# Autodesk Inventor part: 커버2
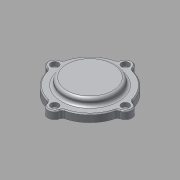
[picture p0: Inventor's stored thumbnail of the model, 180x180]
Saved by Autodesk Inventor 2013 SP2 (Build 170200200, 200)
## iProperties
Company: 한국ATC센터
Created: 2015-12
Part Number: 커버2
Document SubType Name: Modeling
Designer: mdu
Density: 2.71 g/cm^3
Material: 알루미늄 6061
Author: mdu
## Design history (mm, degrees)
sketch "스케치1"
  geometry: C1 r 1.621 at (0, 6.75) reference; C2 r 1.621 at (-37, -30.25) reference; C3 r 1.621 at (0, -67.25) reference; C4 r 1.621 at (37, -30.25) reference; C5 r 10 at (0, -30.25) reference; C6 r 12 at (0, -30.25); C7 r 24.5 at (0, -30.25) reference; A1 r 3 centre (-38.77, -20.408) between (-38.239, -23.361) and (-35.862, -21.146) reference; A2 r 7 centre (-37, -30.25) between (-38.239, -23.361) and (-38.239, -37.139) reference; A3 r 3 centre (-38.77, -40.092) between (-35.862, -39.354) and (-38.239, -37.139) reference; A4 r 37 centre (0, -30.25) between (-35.862, -39.354) and (-9.104, -66.113) reference; A5 r 3 centre (-9.842, -69.02) between (-6.889, -68.489) and (-9.104, -66.113) reference; A6 r 7 centre (0, -67.25) between (-6.889, -68.489) and (6.889, -68.489) reference; A7 r 3 centre (9.842, -69.02) between (9.104, -66.112) and (6.889, -68.489) reference; A8 r 37 centre (0, -30.25) between (9.104, -66.112) and (35.863, -39.354) reference; A9 r 3 centre (38.77, -40.092) between (38.239, -37.139) and (35.863, -39.354) reference; A10 r 7 centre (37, -30.25) between (38.239, -37.139) and (38.239, -23.361) reference; A11 r 3 centre (38.77, -20.408) between (35.863, -21.146) and (38.239, -23.361) reference; A12 r 37 centre (0, -30.25) between (35.863, -21.146) and (9.104, 5.612) reference; A13 r 3 centre (9.842, 8.52) between (6.889, 7.989) and (9.104, 5.612) reference; A14 r 7 centre (0, 6.75) between (6.889, 7.989) and (-6.889, 7.989) reference; A15 r 3 centre (-9.842, 8.52) between (-9.104, 5.612) and (-6.889, 7.989) reference; A16 r 37 centre (0, -30.25) between (-9.104, 5.612) and (-35.862, -21.146) reference; 1 further point
  constraints: 1 centre point, 1 coincident
  dimensions: "d2" = 2 radial gap between concentric circles of C6 C5
extrude "돌출1" new body sketch "스케치1" distance "d0" = 8; taper "d1" = 0 deg
sketch "스케치2"
  geometry: C1 r 23.5 at (0, -30.25) reference; C2 r 12 at (0, -30.25) reference; 1 further point
extrude "돌출2" join sketch "스케치2" distance "d4" = 5; taper "d5" = 0 deg
sketch "스케치3"
  geometry: C1 r 23.5 at (0, 0) reference; C2 r 20.5 at (0, 0); 1 further point
  constraints: 1 centre point
  dimensions: "d6" = 3 radial gap between concentric circles of C2 C1
node "작업 평면1"
extrude "돌출3" join sketch "스케치3" stored distance "d7" = 5; taper "d8" = 0 deg
fillet "모깎기1" dims "d9" = 3
sketch "스케치4"
  geometry: C1 r 12 at (0, -30.25) reference; C2 r 27 at (0, -30.25); 1 further point
  constraints: 1 centre point
  dimensions: "d10" = 15 radial gap between concentric circles of C1 C2
extrude "돌출4" join sketch "스케치4" distance "d11" = 7; taper "d12" = 0 deg
fillet "모깎기2" dims "d13" = 3
chamfer "모따기1" distance "d14" = 1; stored, may be unused: second distance "d15" = 2, angle "d16" = 45 deg
node "작업점1"
  node "작업축1"
chamfer "모따기2" distance "d24" = 1; stored, may be unused: second distance "d25" = 2, angle "d26" = 45 deg
hole "구멍6" diameter "d43" = 4.5; stored, may be unused: countersink angle "d47" = 90 deg, drill point angle "d49" = 118 deg; dims "d41" = 10, "d42" = 10, "d44" = 6, "d45" = 8, "d46" = 4.4, "d48" = 8
fillet "모깎기4" dims "d60" = 3
node "솔리드1"
pattern_circular "원형 패턴1" dims angle "d51" = 360 deg
node "참조1"
node "참조2"
